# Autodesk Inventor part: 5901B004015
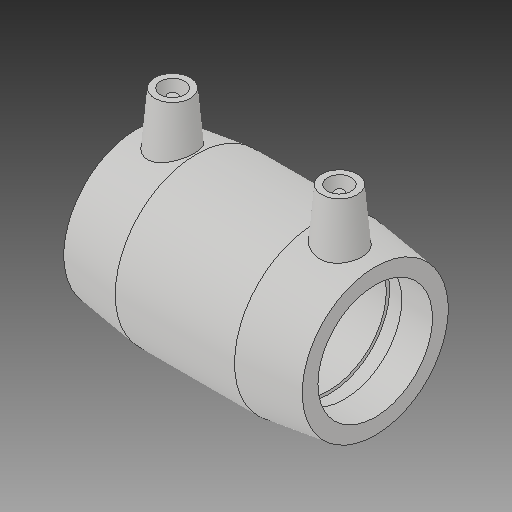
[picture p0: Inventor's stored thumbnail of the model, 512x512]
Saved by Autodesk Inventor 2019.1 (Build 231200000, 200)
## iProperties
Created: 2017-06
Part Number: 5901B004015
Material: Generic
Description: PLASSON IPS COUPLER 1 1/2''
Document SubType Name: Modeling
Designer: KIM
Mass: 8622.19 g
Surface Area: 6772.47 cm^2
Volume: 8622.19 cm^3
Density: 1 g/cm^3
Appearance: Default
Author: KIM
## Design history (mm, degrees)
derived "5901B.ipt"
feature "Solid1::5901B.ipt"
tag "TaggingFeature1"
body "Solid1"
other parameters: "d0" = 100.076, "d1" = 48.1, "d2" = 68.072, "d3" = 48.514, "d4" = 25.019, "d5" = 61.2648, "d6" = 38.48, "d7" = 48.1, "d8" = 168 deg, "d10" = 19.4056, "d11" = 6.46853, "d13" = 100.076, "d14" = 17.6296, "d18" = 48.1, "d19" = 3.52592, "d20" = 168 deg, "d22" = 63.98768, "d23" = 68.072, "d24" = 62.06805, "d25" = 135 deg, "d26" = 45.0342, "d27" = 135 deg, "d29" = 53.086, "d30" = 15, "d31" = 35.0266, "d34" = 5 deg, "d35" = 15, "d39" = 5 deg, "d41" = 4, "d42" = 14, "d43" = 0, "d45" = 4, "d46" = 14, "d47" = 0, "d48" = 3, "d49" = 0, "d50" = 3, "d51" = 0, "d52" = 14.06906, "d53" = 3.51727, "d55" = 48.514, "d_" = 48.1, "L_" = 100.076, "L_1" = 48.514, "D_" = 68.072, "A_" = 53.086, "d_2" = 12, "B_" = 53.086
